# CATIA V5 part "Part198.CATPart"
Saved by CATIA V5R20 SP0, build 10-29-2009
Part number: FA 168700-1
Revision: ANY
Definition: UNKNOWN
Nomenclature: FA 168700-1
Source: Unknown
Bounding box of the stored display mesh (mm): x -3.804 to 3.804, y 0.28 to 2.5, z -4 to 4
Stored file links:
  C:\Users\Utente\Desktop\IO LAVORO\3D X SITO CF\CUMSA\3D files FA\FA 168710-20\Part198.CATPart
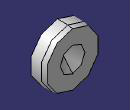
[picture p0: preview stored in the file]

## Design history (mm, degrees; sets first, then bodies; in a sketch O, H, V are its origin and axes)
Body1 "Cortar-Extruir1" (main body)
  Solid1: solid without history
